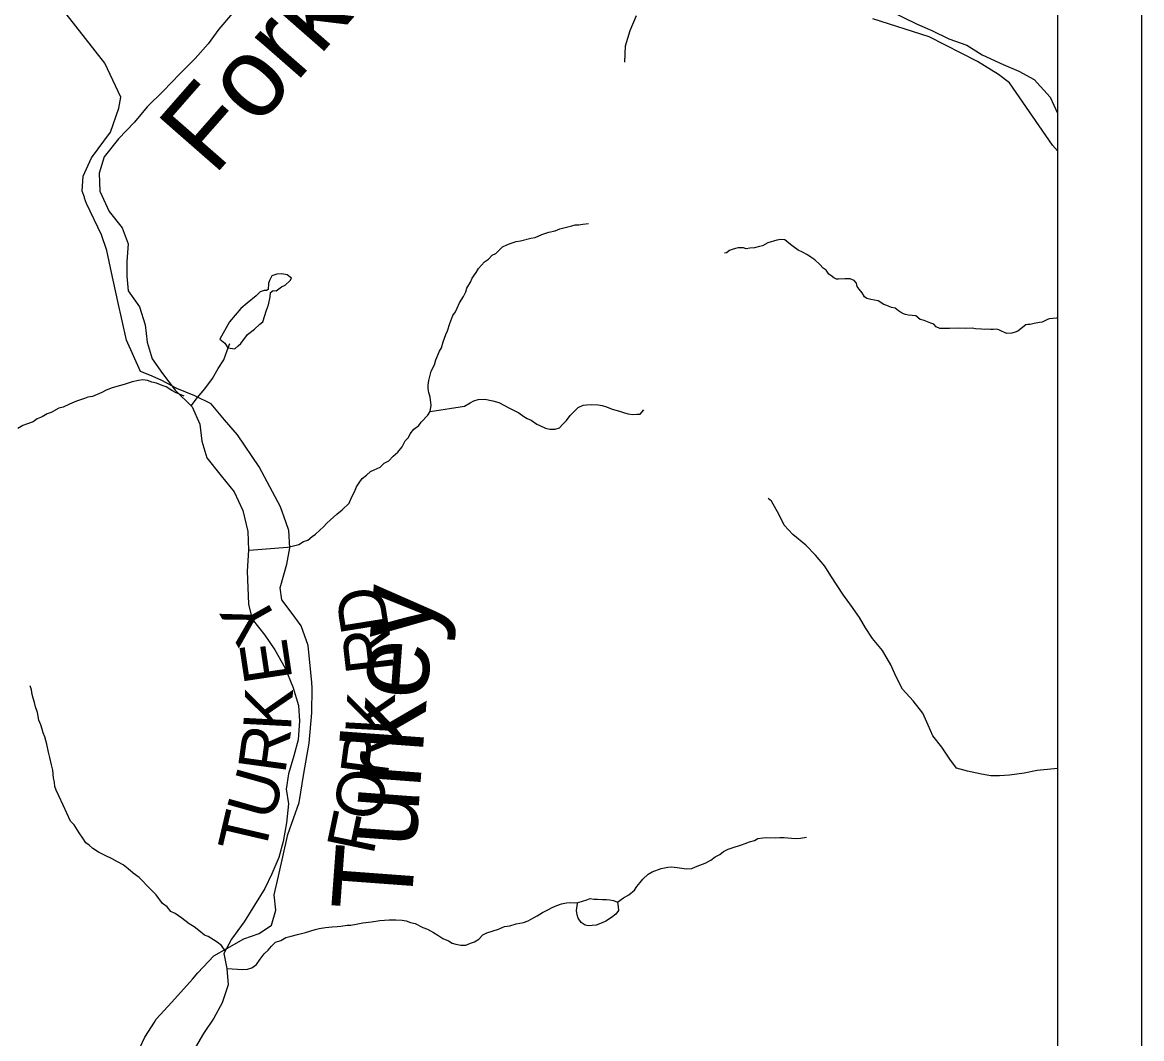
# Model space of a CAD drawing. Extents: x 0 to 34, y 0 to 22.
# Drawn here: x 7.671 to 9, y 16.191 to 17.398 of the extents above; entities that cross this region are included whole.
import ezdxf

# ---------------------------------------------------------------- set-up
doc = ezdxf.new("R2010")
doc.units = 0
for name, color, linetype in [('GM_X_County_Road', 7, 'Continuous'), ('GM_X_Minor_Lake', 7, 'Continuous'), ('GM_X_Minor_River', 7, 'Continuous'), ('GM_X_Minor_River_Text', 7, 'Continuous'), ('GM_X_Township_Road', 7, 'Continuous'), ('GM_X_Township_Road_Text', 7, 'Continuous'), ('SH_Data', 7, 'Continuous')]:
    doc.layers.add(name, color=color, linetype=linetype)

msp = doc.modelspace()

# ---------------------------------------------------------------- linework, layer by layer
at = {"layer": 'GM_X_County_Road'}
msp.add_lwpolyline([(8.9, 17.2458), (8.8943, 17.2527), (8.8431, 17.3268), (8.8302, 17.3365), (8.8053, 17.3519), (8.7476, 17.3814), (8.6809, 17.4025)], dxfattribs=at)
at = {"layer": 'GM_X_Minor_Lake'}
for points in [[(7.9635, 17.0628), (7.9654, 17.0726), (7.9658, 17.0775), (7.9692, 17.0802), (7.9726, 17.0798), (7.979, 17.0844), (7.9832, 17.0863), (7.9892, 17.092), (7.9907, 17.0946), (7.9858, 17.0988), (7.9794, 17.0999), (7.9733, 17.0995), (7.9676, 17.0973), (7.9646, 17.092), (7.9635, 17.0882), (7.9631, 17.0813), (7.9612, 17.0802), (7.9582, 17.0802), (7.9536, 17.0783), (7.9487, 17.0738), (7.9381, 17.065), (7.9305, 17.0586), (7.9241, 17.0506), (7.9173, 17.043), (7.9059, 17.0222), (7.9116, 17.0176), (7.9152, 17.0118)], [(7.9152, 17.0118), (7.9237, 17.0108), (7.9275, 17.0142), (7.9305, 17.0169), (7.9385, 17.0279), (7.9468, 17.034), (7.9532, 17.04), (7.9567, 17.0427), (7.9612, 17.0567), (7.9635, 17.0628)]]:
    msp.add_lwpolyline(points, dxfattribs=at)
at = {"layer": 'GM_X_Minor_River'}
for points in [[(7.9206, 17.4093), (7.9046, 17.3904), (7.8917, 17.3729), (7.8765, 17.3555), (7.8583, 17.3374), (7.8385, 17.3169), (7.8195, 17.298), (7.8043, 17.2798), (7.7854, 17.2601), (7.7686, 17.2389), (7.7625, 17.2192), (7.7632, 17.198), (7.7745, 17.1737), (7.7896, 17.1546), (7.7971, 17.1356), (7.7955, 17.1144), (7.7955, 17.0969), (7.7969, 17.0795), (7.8105, 17.0605), (7.8172, 17.0392), (7.8194, 17.0187), (7.8254, 16.999), (7.8375, 16.9815), (7.8526, 16.9617), (7.8729, 16.9419), (7.882, 16.9214), (7.8842, 16.9009), (7.8902, 16.8812), (7.9075, 16.8599), (7.9226, 16.8409), (7.9331, 16.8188), (7.9391, 16.7938), (7.9398, 16.7718), (7.9382, 16.7467), (7.9396, 16.7073), (7.9441, 16.6898), (7.9591, 16.6708), (7.9712, 16.6533), (7.9833, 16.6313), (7.9923, 16.6093), (7.999, 16.5872), (8.0005, 16.569), (7.9989, 16.5463), (7.9935, 16.5273), (7.9874, 16.5061), (7.9843, 16.4879), (7.9873, 16.4704), (7.985, 16.4477), (7.9811, 16.4257), (7.9757, 16.4068), (7.9674, 16.3871), (7.959, 16.3696), (7.9346, 16.3302), (7.9194, 16.3098), (7.9103, 16.2924), (7.914, 16.2749), (7.9155, 16.2552), (7.9086, 16.234), (7.8987, 16.2158), (7.8865, 16.1976), (7.8713, 16.1719)], [(8.3867, 17.3511), (8.3875, 17.3708), (8.3928, 17.389), (8.4005, 17.4065)], [(8.7002, 17.4125), (8.7335, 17.3964), (8.7509, 17.3888), (8.7713, 17.3789), (8.7925, 17.3712), (8.8106, 17.3598), (8.8355, 17.3483), (8.8544, 17.3407), (8.8726, 17.3308), (8.8914, 17.3095), (8.9, 17.2907)], [(7.9406, 16.7718), (7.9862, 16.7752), (7.9915, 16.7763), (7.9995, 16.7784), (8.0049, 16.7818), (8.0102, 16.7836), (8.0152, 16.788), (8.0194, 16.7906), (8.0244, 16.7955), (8.0286, 16.7992), (8.0329, 16.8037), (8.0371, 16.8078), (8.0448, 16.8145), (8.051, 16.8194), (8.0591, 16.8276), (8.0622, 16.834), (8.0657, 16.8408), (8.0681, 16.8468), (8.0712, 16.8517), (8.0747, 16.8566), (8.0797, 16.8607), (8.0847, 16.8651), (8.0889, 16.867), (8.0962, 16.8703), (8.1008, 16.8748), (8.1062, 16.8777), (8.1116, 16.8833), (8.1169, 16.8882), (8.122, 16.8942), (8.1259, 16.9013), (8.1298, 16.9054), (8.1317, 16.9096), (8.136, 16.9152), (8.1421, 16.9197), (8.1448, 16.9238), (8.1526, 16.932), (8.1553, 16.9365), (8.1566, 16.9437), (8.1556, 16.9533), (8.1538, 16.959), (8.1531, 16.9632), (8.1532, 16.9674), (8.1537, 16.973), (8.1565, 16.9844), (8.1604, 16.9916), (8.162, 16.9976), (8.1664, 17.0078), (8.1687, 17.0119), (8.1708, 17.0191), (8.1739, 17.0278), (8.1759, 17.032), (8.1787, 17.041), (8.1823, 17.0505), (8.1854, 17.0546), (8.1874, 17.0591), (8.1901, 17.0655), (8.1948, 17.0727), (8.1976, 17.0783), (8.1991, 17.0829), (8.2034, 17.09), (8.2054, 17.0945), (8.2101, 17.1013), (8.2128, 17.1062), (8.2198, 17.1141), (8.2248, 17.1174), (8.229, 17.1219), (8.2332, 17.1241), (8.2413, 17.1319), (8.2463, 17.1341), (8.2516, 17.1363), (8.2577, 17.1381), (8.2626, 17.1392), (8.2748, 17.142), (8.2801, 17.1431), (8.2878, 17.1467), (8.2961, 17.1493), (8.3038, 17.151), (8.3095, 17.1532), (8.314, 17.1543), (8.319, 17.1557), (8.3235, 17.1568), (8.3277, 17.1579), (8.3319, 17.1582), (8.3368, 17.1588), (8.3433, 17.1595)], [(8.9, 17.0473), (8.8989, 17.0472), (8.8901, 17.0462), (8.8875, 17.0451), (8.8818, 17.0425), (8.8787, 17.0422), (8.8723, 17.0408), (8.8677, 17.0397), (8.865, 17.0398), (8.8624, 17.0394), (8.8531, 17.0316), (8.8497, 17.0305), (8.8459, 17.0294), (8.8398, 17.0288), (8.8372, 17.03), (8.8338, 17.0319), (8.8305, 17.0335), (8.8274, 17.0339), (8.824, 17.0336), (8.8206, 17.0337), (8.8168, 17.0341), (8.813, 17.0338), (8.81, 17.0342), (8.8028, 17.0343), (8.799, 17.0352), (8.7907, 17.0349), (8.7831, 17.0351), (8.7718, 17.0349), (8.7634, 17.035), (8.7604, 17.0347), (8.7563, 17.037), (8.7533, 17.0401), (8.7499, 17.0413), (8.742, 17.0445), (8.7371, 17.0457), (8.7319, 17.05), (8.7232, 17.0509), (8.7198, 17.0517), (8.7172, 17.0525), (8.7138, 17.0541), (8.7112, 17.0557), (8.7074, 17.0591), (8.7029, 17.06), (8.6976, 17.0623), (8.6939, 17.0635), (8.6871, 17.0678), (8.6784, 17.0695), (8.6739, 17.0707), (8.6709, 17.0723), (8.6684, 17.0773), (8.6646, 17.0815), (8.6624, 17.0846), (8.6614, 17.0888), (8.6588, 17.0919), (8.6542, 17.0938), (8.6478, 17.094), (8.6402, 17.0933), (8.6376, 17.0934), (8.6346, 17.0949), (8.6312, 17.098), (8.6286, 17.0996), (8.6256, 17.1042), (8.6219, 17.1066), (8.6182, 17.1108), (8.6122, 17.1166), (8.6074, 17.1197), (8.6032, 17.1224), (8.5976, 17.1256), (8.5924, 17.1279), (8.5864, 17.1322), (8.583, 17.1346), (8.5789, 17.1381), (8.5763, 17.14), (8.5717, 17.1405), (8.5668, 17.1398), (8.5561, 17.1365), (8.55, 17.1332), (8.5462, 17.1321), (8.5405, 17.1307), (8.5348, 17.1301), (8.5306, 17.1297), (8.5272, 17.1306), (8.5212, 17.1307), (8.5178, 17.13), (8.514, 17.1289), (8.5109, 17.1274), (8.5074, 17.1248), (8.5048, 17.1245)], [(7.8717, 16.9432), (7.8794, 16.9528), (7.8881, 16.9631), (7.8972, 16.9756), (7.9037, 16.9873), (7.9105, 16.9976), (7.9143, 17.0089), (7.9177, 17.0169)], [(7.8632, 16.9547), (7.8579, 16.9567), (7.8538, 16.9583), (7.8489, 16.9614), (7.8422, 16.9657), (7.8373, 16.967), (7.8305, 16.9701), (7.8252, 16.9713), (7.82, 16.973), (7.8143, 16.9738), (7.809, 16.9731), (7.8018, 16.9714), (7.7922, 16.9685), (7.7877, 16.967), (7.7778, 16.9645), (7.7709, 16.9616), (7.7655, 16.9587), (7.7545, 16.9543), (7.7492, 16.9532), (7.745, 16.9518), (7.7354, 16.9485), (7.7274, 16.9452), (7.7198, 16.9416), (7.7145, 16.9401), (7.7057, 16.935), (7.7007, 16.9335), (7.695, 16.9298), (7.6889, 16.9277), (7.6843, 16.9239), (7.6763, 16.9214), (7.6717, 16.9196), (7.6659, 16.9163)], [(8.1553, 16.9365), (8.1963, 16.9427), (8.2028, 16.9468), (8.2074, 16.949), (8.2124, 16.9504), (8.2203, 16.951), (8.2298, 16.949), (8.2369, 16.947), (8.2497, 16.9403), (8.2561, 16.9371), (8.2606, 16.9348), (8.2665, 16.9305), (8.2707, 16.9281), (8.2752, 16.9262), (8.2819, 16.9211), (8.2864, 16.9191), (8.2924, 16.9164), (8.2973, 16.9152), (8.3038, 16.9154), (8.3091, 16.9169), (8.313, 16.9214), (8.3172, 16.9258), (8.3215, 16.9315), (8.3261, 16.936), (8.3311, 16.9412), (8.3369, 16.9438), (8.341, 16.9444), (8.3467, 16.9447), (8.3547, 16.9442), (8.3596, 16.9434), (8.3648, 16.9418), (8.3716, 16.939), (8.3773, 16.9374), (8.3814, 16.9365), (8.3863, 16.9349), (8.3905, 16.9337), (8.3958, 16.9329), (8.4007, 16.9332), (8.4048, 16.9331), (8.4091, 16.9384)], [(8.9, 16.5125), (8.8963, 16.5118), (8.8762, 16.5099), (8.8607, 16.5069), (8.8433, 16.5042), (8.8312, 16.5035), (8.8209, 16.5035), (8.81, 16.5057), (8.7933, 16.5091), (8.7801, 16.5126), (8.7725, 16.5232), (8.763, 16.5376), (8.7521, 16.5512), (8.7468, 16.5637), (8.7404, 16.5781), (8.729, 16.5925), (8.7161, 16.6065), (8.7086, 16.6213), (8.7021, 16.6353), (8.6923, 16.6524), (8.6806, 16.6668), (8.6723, 16.6793), (8.6651, 16.6918), (8.6549, 16.7062), (8.6461, 16.7183), (8.631, 16.741), (8.6238, 16.7528), (8.6129, 16.7657), (8.6015, 16.7774), (8.586, 16.7903), (8.5758, 16.8013), (8.5697, 16.8134), (8.5606, 16.8297), (8.5565, 16.8331)], [(7.9119, 16.2958), (7.9078, 16.302), (7.9026, 16.3059), (7.8984, 16.3087), (7.8917, 16.3126), (7.8876, 16.3145), (7.8808, 16.32), (7.8752, 16.3242), (7.8692, 16.3278), (7.8606, 16.3344), (7.8528, 16.3402), (7.8475, 16.3426), (7.8431, 16.348), (7.8375, 16.3519), (7.8301, 16.3622), (7.823, 16.3692), (7.81, 16.3827), (7.8029, 16.3881), (7.7969, 16.3932), (7.7909, 16.3978), (7.7842, 16.4014), (7.7778, 16.4049), (7.7688, 16.4092), (7.7616, 16.4131), (7.7549, 16.4171), (7.7508, 16.4213), (7.7467, 16.424), (7.743, 16.4294), (7.7389, 16.4359), (7.733, 16.4455), (7.7286, 16.4498), (7.7242, 16.4594), (7.7198, 16.4686), (7.7147, 16.48), (7.7114, 16.4866), (7.71, 16.4911), (7.7093, 16.4957), (7.7083, 16.5014), (7.7073, 16.5102), (7.7059, 16.5167), (7.7041, 16.5254), (7.7024, 16.5319), (7.7003, 16.5414), (7.6978, 16.5498), (7.696, 16.5548), (7.6949, 16.559), (7.6931, 16.564), (7.6909, 16.5697), (7.6892, 16.5789), (7.687, 16.5854), (7.6856, 16.5907), (7.6842, 16.5957), (7.6831, 16.6002), (7.6821, 16.6056), (7.6806, 16.6105)], [(8.378, 16.3534), (8.3849, 16.3586), (8.3914, 16.3623), (8.3979, 16.3679), (8.4007, 16.372), (8.4049, 16.3769), (8.408, 16.381), (8.4142, 16.387), (8.4188, 16.3896), (8.4295, 16.3936), (8.4374, 16.3953), (8.4416, 16.3957), (8.4488, 16.3948), (8.4597, 16.3931), (8.4662, 16.3937), (8.4704, 16.3956), (8.4757, 16.3974), (8.4818, 16.3999), (8.4887, 16.4036), (8.4937, 16.4073), (8.4991, 16.4103), (8.5037, 16.4136), (8.509, 16.4166), (8.514, 16.418), (8.525, 16.4216), (8.5292, 16.4231), (8.5346, 16.4252), (8.5403, 16.4267), (8.5445, 16.4293), (8.5502, 16.4299), (8.5543, 16.4302), (8.5649, 16.4301), (8.5706, 16.4303), (8.5755, 16.4303), (8.5843, 16.4297), (8.5899, 16.4293), (8.5949, 16.4296), (8.6021, 16.4306)], [(7.914, 16.2749), (7.933, 16.2735), (7.9387, 16.2738), (7.9437, 16.2756), (7.9491, 16.2797), (7.9537, 16.2857), (7.9584, 16.2921), (7.963, 16.2966), (7.9669, 16.3011), (7.9719, 16.3059), (7.9783, 16.3081), (7.9841, 16.3114), (7.9906, 16.3132), (7.9978, 16.315), (8.0073, 16.3175), (8.0191, 16.3211), (8.0237, 16.3221), (8.0313, 16.3235), (8.0389, 16.3242), (8.0449, 16.3248), (8.0495, 16.3251), (8.0567, 16.3261), (8.0612, 16.3264), (8.0677, 16.3275), (8.0753, 16.3289), (8.0859, 16.3302), (8.0958, 16.3316), (8.1068, 16.3325), (8.1148, 16.3324), (8.1223, 16.3323), (8.1269, 16.3314), (8.1321, 16.3294), (8.1378, 16.3282), (8.1468, 16.3235), (8.1524, 16.3215), (8.1592, 16.3176), (8.1644, 16.3145), (8.1704, 16.3105), (8.1772, 16.3078), (8.1817, 16.305), (8.1858, 16.3038), (8.1919, 16.3026), (8.1976, 16.3025), (8.2033, 16.3047), (8.2079, 16.3065), (8.2132, 16.3098), (8.2178, 16.3147), (8.2228, 16.3173), (8.2365, 16.3216), (8.2438, 16.3245), (8.2499, 16.3256), (8.2575, 16.3277), (8.2662, 16.3295), (8.2719, 16.3313), (8.2773, 16.3346), (8.2826, 16.3375), (8.2888, 16.3412), (8.2953, 16.3445), (8.3002, 16.3471), (8.3056, 16.3497), (8.3113, 16.3515), (8.3174, 16.3529), (8.3223, 16.3532), (8.3265, 16.3528), (8.331, 16.3531), (8.3413, 16.3563), (8.3455, 16.3578), (8.3497, 16.3573), (8.3542, 16.3572), (8.3599, 16.3568), (8.3648, 16.3567), (8.3689, 16.3562), (8.3731, 16.3554), (8.378, 16.3534), (8.3787, 16.3481), (8.379, 16.3435), (8.3759, 16.3394), (8.3705, 16.3353), (8.364, 16.3309), (8.3598, 16.329), (8.3525, 16.3261), (8.3476, 16.3258), (8.3434, 16.3255), (8.3393, 16.3263), (8.3348, 16.3294), (8.3311, 16.3344), (8.33, 16.3386), (8.3293, 16.3436), (8.3302, 16.3519), (8.3306, 16.353)]]:
    msp.add_lwpolyline(points, dxfattribs=at)
at = {"layer": 'GM_X_Township_Road'}
for points in [[(7.7449, 17.1907), (7.7425, 17.1979), (7.7436, 17.2158), (7.7535, 17.2375), (7.776, 17.2682), (7.7858, 17.2964), (7.7881, 17.3097), (7.7692, 17.3499), (7.7233, 17.4085), (7.7104, 17.4195), (7.7066, 17.4248), (7.7077, 17.4343), (7.721, 17.4583), (7.7207, 17.478), (7.7192, 17.497), (7.7298, 17.5182)], [(7.9843, 16.8041), (7.9776, 16.8229), (7.9526, 16.8707), (7.9268, 16.9084), (7.9113, 16.9266), (7.8953, 16.9456), (7.876, 16.9551), (7.8547, 16.9635), (7.8361, 16.9734), (7.8228, 16.9794), (7.8114, 16.984), (7.7951, 17.0212), (7.7845, 17.0668), (7.7773, 17.1014), (7.7717, 17.1276), (7.7652, 17.1463), (7.7474, 17.1835), (7.7452, 17.1898), (7.7449, 17.1907)], [(8.0148, 16.6145), (8.0105, 16.6584), (8.0022, 16.6819), (7.9905, 16.6979), (7.9794, 16.7127), (7.9772, 16.7268), (7.9852, 16.7549), (7.989, 16.7742), (7.9875, 16.7951), (7.9843, 16.8041)], [(7.8281, 16.2111), (7.8301, 16.2144), (7.8488, 16.2349), (7.8732, 16.2623), (7.8796, 16.2695), (7.8986, 16.29), (7.9142, 16.2987), (7.9343, 16.3101), (7.9525, 16.3165), (7.967, 16.3264), (7.9723, 16.3442), (7.9704, 16.3621), (7.9754, 16.3845), (7.9864, 16.4339), (8.0001, 16.4719), (8.0055, 16.5064), (8.0116, 16.5425), (8.015, 16.5786), (8.0154, 16.6078), (8.0148, 16.6145)], [(7.706, 15.87), (7.7091, 15.9026), (7.7148, 15.9478), (7.719, 15.9721), (7.7285, 15.9934), (7.7411, 16.0135), (7.7476, 16.0374), (7.7483, 16.064), (7.7484, 16.0849), (7.7537, 16.1016), (7.7559, 16.1046), (7.7663, 16.1187), (7.7773, 16.1309), (7.7921, 16.1491), (7.805, 16.1677), (7.8168, 16.1931), (7.8281, 16.2111)]]:
    msp.add_lwpolyline(points, dxfattribs=at)
at = {"layer": 'SH_Data'}
for p, q in [((9, 21), (9, 14)), ((8.9, 20.9), (8.9, 14.1))]:
    msp.add_line(p, q, dxfattribs=at)

# ---------------------------------------------------------------- texts
at = {"layer": 'GM_X_Minor_River_Text'}
for s, height, rotation, p in [('Fork', 0.09473, 48.7821, (7.8987, 17.215)), ('Turkey', 0.09471, 85.7613, (8.1325, 16.3401))]:
    msp.add_text(s, height=height, rotation=rotation, dxfattribs=at).set_placement(p)
at = {"layer": 'GM_X_Township_Road_Text'}
for s, rotation, p in [('D', 99.1344, (8.1069, 16.6777)), ('Y', 119.4879, (7.9785, 16.6814)), ('R', 96.5551, (8.1126, 16.6286)), ('E', 98.5487, (7.9921, 16.6184)), ('K', 87.0193, (7.9901, 16.5562)), ('K', 86.8179, (8.1112, 16.5507)), ('R', 82.2469, (7.9833, 16.5049)), ('R', 82.4873, (8.1047, 16.4997)), ('U', 74.1872, (7.9679, 16.4484)), ('O', 80.5916, (8.0962, 16.4484)), ('T', 76.8304, (7.9584, 16.4077)), ('F', 78.1559, (8.0878, 16.4083))]:
    msp.add_text(s, height=0.0568, rotation=rotation, dxfattribs=at).set_placement(p)

doc.saveas('drawing.dxf')
